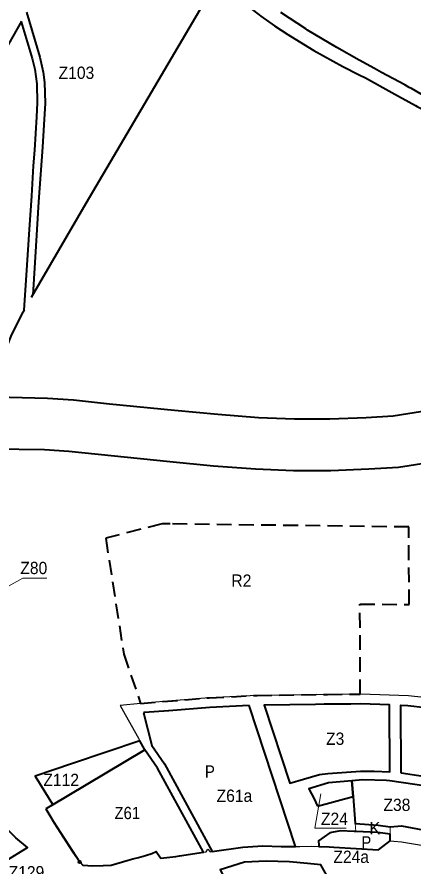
# Model space of a CAD drawing. Extents: x -650276 to -642489, y -1074311 to -1066658.
# Drawn here: x -647810 to -647038, y -1069867 to -1068210 of the extents above; entities that cross this region are included whole.
import ezdxf

# ---------------------------------------------------------------- set-up
doc = ezdxf.new("R2010")
doc.units = 0
doc.header["$LTSCALE"] = 9.6
doc.header["$PDMODE"] = 32
doc.header["$PDSIZE"] = 4.8
doc.linetypes.add('MEDIUM_DASHED', pattern=[4.5, 3, -1.5])
for name, color, linetype, lineweight in [('2', 7, 'Continuous', 40), ('42', 7, 'Continuous', 25), ('44', 7, 'Continuous', 40), ('45', 7, 'Continuous', 40), ('46', 7, 'Continuous', 13), ('47', 7, 'Continuous', 13), ('48', 7, 'Continuous', 35), ('60', 7, 'Continuous', 35), ('61', 7, 'MEDIUM_DASHED', 40), ('62', 7, 'Continuous', 35)]:
    doc.layers.add(name, color=color, linetype=linetype, lineweight=lineweight)

msp = doc.modelspace()

# ---------------------------------------------------------------- linework, layer by layer
at = {"layer": '2'}
msp.add_lwpolyline([(-647833.172, -1069855.944), (-647833.172, -1069855.944), (-647831.62, -1069854.99), (-647789.55, -1069829.12), (-647811.83, -1069810.39), (-647827.16, -1069795.32), (-647831.32, -1069806.56), (-647833.91, -1069808.91), (-647833.2, -1069854.15)], close=True, dxfattribs=at)
at = {"layer": '42'}
for points in [[(-646986.633, -1069539.757), (-647046.325, -1069533.275), (-647140.008, -1069530.068), (-647204.293, -1069530.647), (-647341.697, -1069532.602), (-647434.969, -1069537.141), (-647523.931, -1069544.499), (-647568.792, -1069548.21), (-647608.81, -1069551.868), (-647598.735, -1069570.026), (-647573.15, -1069616.16), (-647570.37, -1069621.18), (-647570.37, -1069621.18), (-647701.61, -1069665.279), (-647774.11, -1069689.64), (-647740.74, -1069744.24), (-647742.36, -1069746.93), (-647752.32, -1069752.95), (-647753.7, -1069753.9), (-647745.84, -1069766.71), (-647687.45, -1069857.15), (-647681.51, -1069863.72), (-647661.79, -1069864.92), (-647641.78, -1069864.26), (-647625.83, -1069863.19), (-647593.07, -1069853.74), (-647572.63, -1069848.63), (-647559.47, -1069844.92), (-647547.12, -1069840.87), (-647538.34, -1069836.68), (-647531.33, -1069847.23), (-647529.5, -1069849.99), (-647492.76, -1069845.02), (-647441.19, -1069837.6), (-647437.46, -1069832.27), (-647433.32, -1069837.33), (-647369.3, -1069828.22), (-647330.46, -1069825.51), (-647294.38, -1069826.88)], [(-647294.38, -1069826.88), (-647270.09, -1069827.02), (-647258.143, -1069827.094), (-647235.49, -1069826.51)], [(-647235.49, -1069826.51), (-647205.603, -1069827.72), (-647191.66, -1069828.58), (-647201.106, -1069827.997), (-647191.66, -1069828.58), (-647104.741, -1069833.568), (-647082.145, -1069816.321), (-647074.72, -1069816.8), (-647060.029, -1069817.854), (-646993.81, -1069829.12)]]:
    msp.add_lwpolyline(points, dxfattribs=at)
at = {"layer": '44'}
for points in [[(-647781.204, -1068756.329), (-647675.054, -1068572.919), (-647461.188, -1068209.373), (-647419.713, -1068138.871), (-647472.338, -1068093.096), (-647553.628, -1067999.427), (-647618.773, -1067899.915), (-647618.773, -1067899.914)], [(-647419.713, -1068138.871), (-647405.71, -1068151.74), (-647372.38, -1068179.01), (-647337.74, -1068205.67), (-647334.62, -1068208.02), (-647307.39, -1068227.44), (-647281.64, -1068244.34), (-647234.11, -1068273.04), (-647230.83, -1068274.93), (-647174.56, -1068306.35), (-647142.788, -1068322.462), (-647130.29, -1068328.8), (-647079.16, -1068357.01), (-647032.91, -1068382.51), (-647029.23, -1068384.46), (-646997.06, -1068401.37), (-646929.56, -1068435.42), (-646927.06, -1068436.66)], [(-647791.055, -1068200.507), (-647765.22, -1068287.94), (-647758.45, -1068317.66), (-647756.09, -1068337.61), (-647754.99, -1068378.21), (-647757.41, -1068419.98), (-647760.22, -1068463.96), (-647768.02, -1068570.36), (-647772.85, -1068656.41), (-647778.967, -1068752.463)], [(-647002.71, -1068371.09), (-647040.77, -1068349.4), (-647044.93, -1068347.08), (-647053.75, -1068342.11), (-647099.2, -1068318.27), (-647112.813, -1068310.564), (-647142.41, -1068293.81), (-647186.26, -1068269.45), (-647243.39, -1068235.26), (-647246.8, -1068233.08), (-647295.47, -1068201.09)], [(-647801.168, -1068218.237), (-647843.6, -1068292.629), (-647868.214, -1068337.803), (-647914.339, -1068432.512), (-647946.187, -1068510.254), (-647971.074, -1068581.98), (-647997.27, -1068674.747), (-648011.775, -1068739.718), (-648023.914, -1068809.332), (-648030.73, -1068861.213), (-648038.596, -1068968.281), (-647958.168, -1068957.73)], [(-647801.797, -1068219.339), (-647780.07, -1068290.53), (-647774.94, -1068311.47), (-647770.81, -1068340.29), (-647770.12, -1068377.5), (-647771.74, -1068404.5), (-647775.82, -1068469.74), (-647778.24, -1068499.95), (-647781.55, -1068558.38), (-647785.79, -1068623.98), (-647791.77, -1068713.23), (-647796.139, -1068781.67)], [(-647065.688, -1069087.73), (-646978.92, -1069073.93), (-646929.186, -1069052.925), (-646880.163, -1069024.903), (-646829.104, -1068987.917), (-646782.784, -1068941.581), (-646741.85, -1068895.719), (-646673.05, -1068812.491), (-646618.655, -1068742.359), (-646617.991, -1068741.504)], [(-647864.531, -1068951.823), (-647846.989, -1068896.545), (-647820.883, -1068832.117), (-647797.632, -1068784.713), (-647795.185, -1068780.485)], [(-647749.978, -1068953.416), (-647850.043, -1068951.099), (-647864.531, -1068951.823), (-647895.901, -1068953.392), (-647958.168, -1068957.73), (-648038.596, -1068968.281), (-648038.596, -1068968.281), (-648038.746, -1068968.301), (-648058.764, -1068970.927)], [(-646934.465, -1068940.759), (-646973.61, -1068963.135), (-647006.63, -1068977.08), (-647076.422, -1068988.18), (-647128.674, -1068991.167), (-647199.672, -1068994.255), (-647268.348, -1068994.255), (-647338.816, -1068991.19), (-647417.895, -1068984.986), (-647502.412, -1068977.157), (-647629.424, -1068964.608), (-647699.561, -1068956.635), (-647749.978, -1068953.416)], [(-647886.615, -1069053.052), (-647856.541, -1069051.548), (-647756.441, -1069053.207), (-647708.401, -1069056.275), (-647511.94, -1069076.703), (-647426.417, -1069084.624), (-647344.902, -1069091.02), (-647270.522, -1069094.255), (-647197.498, -1069094.255), (-647123.648, -1069091.043), (-647065.688, -1069087.73)]]:
    msp.add_lwpolyline(points, dxfattribs=at)
at = {"layer": '44', "lineweight": 13}
msp.add_lwpolyline([(-647751.811, -1069303.761), (-647798.61, -1069303.761), (-647856.005, -1069335.572)], dxfattribs=at)
msp.add_lwpolyline([(-647751.811, -1069303.761), (-647798.61, -1069303.761), (-647856.005, -1069335.572)], dxfattribs=at)
at = {"layer": '45'}
for points in [[(-647251.002, -1069695.852), (-647219.628, -1069686.746), (-647203.374, -1069684.716), (-647139.649, -1069679.961), (-647113.255, -1069679.966), (-647082.761, -1069681.399), (-647083.356, -1069551.018), (-647140.247, -1069549.071), (-647158.572, -1069549.252), (-647211.05, -1069549.77), (-647227.623, -1069550.23), (-647327.682, -1069551.263), (-647277.71, -1069703.421)], [(-647251.002, -1069695.852), (-647219.628, -1069686.746), (-647203.374, -1069684.716), (-647139.649, -1069679.961), (-647113.255, -1069679.966), (-647082.761, -1069681.399), (-647083.356, -1069551.018), (-647140.247, -1069549.071), (-647158.572, -1069549.252), (-647211.05, -1069549.77), (-647227.623, -1069550.23), (-647327.682, -1069551.263), (-647277.71, -1069703.421)], [(-647060.7, -1069683.894), (-647061.304, -1069551.773), (-647047.648, -1069552.245), (-646944.168, -1069563.743), (-646846, -1069575), (-646863, -1069714)], [(-647060.7, -1069683.894), (-647061.304, -1069551.773), (-647047.648, -1069552.245), (-646944.168, -1069563.743), (-646846, -1069575), (-646863, -1069714)], [(-647060.617, -1069702.116), (-647082.682, -1069698.791), (-647089.456, -1069698.579), (-647135.585, -1069697.137), (-647156.782, -1069698.901), (-647154.33, -1069729.69), (-647150.138, -1069782.334), (-647105.334, -1069785.168), (-647082.271, -1069788.81), (-647060.23, -1069786.932), (-646952.56, -1069807.13), (-646980.4, -1069746.98), (-646998.56, -1069711.443)], [(-647223.66, -1069748.26), (-647154.33, -1069729.69), (-647156.782, -1069698.901), (-647202.181, -1069702.678), (-647240.994, -1069714.513), (-647230.16, -1069734.42)], [(-647223.66, -1069748.26), (-647154.33, -1069729.69), (-647156.782, -1069698.901), (-647202.181, -1069702.678), (-647240.994, -1069714.513), (-647230.16, -1069734.42)], [(-647196.616, -1069800.068), (-647199.65, -1069800.69), (-647221.87, -1069816.21), (-647221.28, -1069824.74), (-647221.14, -1069826.761), (-647201.106, -1069827.997), (-647191.66, -1069828.58), (-647104.741, -1069833.568), (-647082.145, -1069816.321), (-647082.206, -1069802.916), (-647096.39, -1069801.15), (-647107.04, -1069799.84), (-647148.9, -1069797.88), (-647152.39, -1069797.7), (-647178.73, -1069796.4)], [(-647365.866, -1069857.774), (-647413.461, -1069872.442), (-647343.28, -1070003.81), (-647339.69, -1070001.95), (-647330.5, -1069997.19), (-647304.05, -1069983.79), (-647294.257, -1070002.745), (-647242.254, -1069980.33), (-647229.096, -1069974.658), (-647235, -1069963), (-647176.499, -1069938.333), (-647205.781, -1069883.796), (-647217.177, -1069862.57), (-647243.231, -1069860.34), (-647278.525, -1069857.002), (-647323.794, -1069855.468)], [(-647365.866, -1069857.774), (-647413.461, -1069872.442), (-647343.28, -1070003.81), (-647339.69, -1070001.95), (-647330.5, -1069997.19), (-647304.05, -1069983.79), (-647294.257, -1070002.745), (-647242.254, -1069980.33), (-647229.096, -1069974.658), (-647235, -1069963), (-647176.499, -1069938.333), (-647205.781, -1069883.796), (-647217.177, -1069862.57), (-647243.231, -1069860.34), (-647278.525, -1069857.002), (-647323.794, -1069855.468)]]:
    msp.add_lwpolyline(points, close=True, dxfattribs=at)
for points in [[(-647356.899, -1069552.034), (-647433.779, -1069556.106), (-647433.779, -1069556.106), (-647513.66, -1069562.249), (-647514.067, -1069562.282), (-647560.836, -1069566.036), (-647563.104, -1069566.28)], [(-647369.3, -1069828.22), (-647330.46, -1069825.51), (-647294.38, -1069826.88), (-647270.09, -1069827.02), (-647266.581, -1069827.042), (-647356.899, -1069552.034)], [(-647563.104, -1069566.28), (-647546.777, -1069629.901), (-647521.943, -1069665.763)], [(-647570.37, -1069621.18), (-647701.61, -1069665.279), (-647774.11, -1069689.64), (-647740.74, -1069744.24), (-647742.36, -1069746.93), (-647674.901, -1069706.701)], [(-647570.37, -1069621.18), (-647701.61, -1069665.279), (-647774.11, -1069689.64), (-647740.74, -1069744.24), (-647742.36, -1069746.93), (-647674.901, -1069706.701)], [(-647674.901, -1069706.701), (-647560.36, -1069638.39), (-647570.37, -1069621.18)], [(-647674.901, -1069706.701), (-647560.36, -1069638.39), (-647570.37, -1069621.18)], [(-647560.36, -1069638.39), (-647674.901, -1069706.701), (-647742.36, -1069746.93)], [(-647446.322, -1069838.338), (-647535.588, -1069674.163), (-647560.36, -1069638.39)], [(-647521.943, -1069665.763), (-647428.993, -1069836.714), (-647369.3, -1069828.22)], [(-647742.36, -1069746.93), (-647752.32, -1069752.95), (-647753.7, -1069753.9)], [(-647753.7, -1069753.9), (-647751.66, -1069757.12), (-647745.84, -1069766.71), (-647737.17, -1069780.85), (-647700.58, -1069837.2), (-647687.45, -1069857.15), (-647681.51, -1069863.72)], [(-647641.78, -1069864.26), (-647625.83, -1069863.19), (-647593.07, -1069853.74), (-647583.62, -1069851.13), (-647572.63, -1069848.63), (-647559.47, -1069844.92), (-647547.12, -1069840.87), (-647538.34, -1069836.68), (-647536.82, -1069838.87), (-647531.33, -1069847.23), (-647529.5, -1069849.99), (-647500.03, -1069846.28), (-647492.76, -1069845.02), (-647446.322, -1069838.338)], [(-647681.51, -1069863.72), (-647661.79, -1069864.92), (-647641.78, -1069864.26)]]:
    msp.add_lwpolyline(points, dxfattribs=at)
msp.add_point((-647687.45, -1069857.15), dxfattribs=at)
at = {"layer": '46'}
msp.add_lwpolyline([(-647167.693, -1069791.112), (-647229.126, -1069791.112), (-647217.012, -1069724.439)], dxfattribs=at)
msp.add_lwpolyline([(-647167.693, -1069791.112), (-647229.126, -1069791.112), (-647217.012, -1069724.439)], dxfattribs=at)
at = {"layer": '47'}
for p, q in [((-647150.141, -1069782.334), (-647148.9, -1069797.88)), ((-647107.04, -1069799.84), (-647096.39, -1069801.15))]:
    msp.add_line(p, q, dxfattribs=at)
for points in [[(-647082.271, -1069788.81), (-647105.334, -1069785.168), (-647105.334, -1069785.168), (-647150.138, -1069782.334)], [(-647096.39, -1069801.15), (-647096.39, -1069801.15), (-647082.206, -1069802.917), (-647082.271, -1069788.81)], [(-647148.9, -1069797.88), (-647148.9, -1069797.88), (-647107.04, -1069799.84)]]:
    msp.add_lwpolyline(points, dxfattribs=at)
at = {"layer": '61'}
msp.add_lwpolyline([(-647045.7, -1069204.106), (-647511.107, -1069198.223), (-647526.615, -1069198.093), (-647636.743, -1069226.014), (-647601.568, -1069452.14), (-647568.792, -1069548.21), (-647434.969, -1069537.141), (-647341.697, -1069532.602), (-647204.293, -1069530.647), (-647140.334, -1069530.057), (-647141.134, -1069354.872), (-647045.123, -1069355.003)], close=True, dxfattribs=at)

# ---------------------------------------------------------------- texts
at = {"layer": '2', "width": 0.95}
msp.add_text('Z129', height=24, dxfattribs=at).set_placement((-647826.051, -1069889.189))
at = {"layer": '44', "width": 0.95}
for s, p in [('Z103', (-647728.595, -1068330.624)), ('Z103', (-647728.595, -1068330.624)), ('Z80', (-647803.311, -1069296.044)), ('Z80', (-647803.311, -1069296.044))]:
    msp.add_text(s, height=24, dxfattribs=at).set_placement(p)
at = {"layer": '46'}
for s, width, p in [('Z3', 0.95, (-647207.094, -1069628.872)), ('Z3', 0.95, (-647207.094, -1069628.872)), ('Z112', 0.95, (-647758.383, -1069709.22)), ('Z112', 0.95, (-647758.383, -1069709.22)), ('Z61a', 0.95, (-647420.53, -1069740.066)), ('Z38', 0.95, (-647095.223, -1069757.854)), ('Z38', 0.95, (-647095.223, -1069757.854)), ('Z61', 0.9, (-647619.576, -1069773.738)), ('Z24', 0.95, (-647217.069, -1069785.057)), ('Z24', 0.95, (-647217.069, -1069785.057)), ('Z24a', 0.95, (-647192.847, -1069859.131))]:
    msp.add_text(s, height=24, dxfattribs=dict(at, width=width)).set_placement(p)
at = {"layer": '48'}
msp.add_text('K', height=24, dxfattribs=at).set_placement((-647122.713, -1069803.226))
at = {"layer": '60', "width": 0.9}
for p in [(-647443.274, -1069692.913), (-647443.274, -1069692.913), (-647138.27, -1069830.996), (-647138.27, -1069830.996)]:
    msp.add_text('P', height=24, dxfattribs=at).set_placement(p)
at = {"layer": '62', "width": 0.95}
msp.add_text('R2', height=24, dxfattribs=at).set_placement((-647391.654, -1069320.724))
msp.add_text('R2', height=24, dxfattribs=at).set_placement((-647391.654, -1069320.724))

doc.saveas('drawing.dxf')
